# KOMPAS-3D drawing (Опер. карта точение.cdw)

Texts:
  Размерные надписи
  Линия-выноска #2
  Сталь 45 ГОСТ1050-88
  ПТСДМ.012.КР.00.00.00.00.ПЗ
  Содержание перехода
  Инструмент
  Вспомогательный
  Режущий
  Измерительный
  Расч. размер
  диамметр,
  ширина,мм
  Длина,мм
  t,мм
  S,мм/об
  n,об/мин
  V,м/мин
  Режим работы
  Номер
  цеха
  участка
  операции
  Наименование операции
  Наименование и марка материала
  детали
  Заготовка
  Размеры
  Количество одновременно
  обрабатываемых деталей
  Приспособление
  Охлаждение
  Операционная карта механической обработки
  БрГУ
  Токарная
  Оборудование (наименование, модель)
  Разраб.
  Пров.
  Дата
  Подп.
  Плеханов Г.Н.
  Центры
  вращающийся и
  неподвижный
  проходной упорный
  отогнутый резец
  Точить поверхность 1 начерно
  Установить заготовку
  Снять заготовку
  токарно-винторезный станок 16К20
  Есть
  Точить поверхность 1 начисто
  Пешков М.А.
  Лист
  Изм.
  № докум.
  Стили документа
Dimensions and other numbers on the sheet: 1; 2; 0,2; 7; 6; 5; 4; 3; 18; 0,6; 1000; 210; 0,23; 0,1; 170; 64; 2,5; 3,2; 0,25; 1600; 336; 0,35; 1:1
